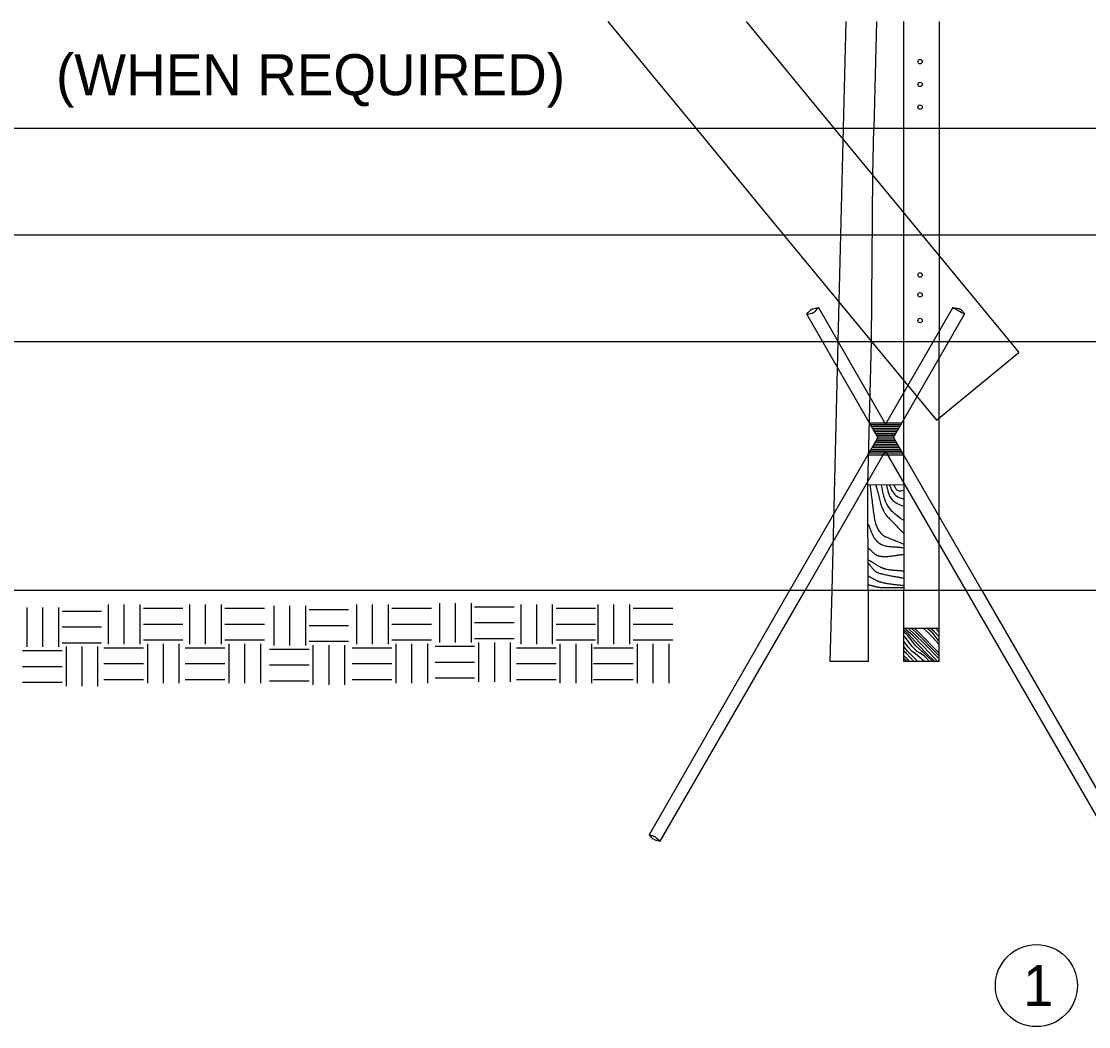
# Model space of a CAD drawing. Extents: x 49991 to 79985, y 47703 to 60542.
# Drawn here: x 50002.281 to 50003.842, y 49994.126 to 49995.596 of the extents above; entities that cross this region are included whole.
import ezdxf

# ---------------------------------------------------------------- set-up
doc = ezdxf.new("R2010")
doc.units = 0
for name, color, linetype in [('Level 1', 7, 'Continuous'), ('Level 2', 7, 'Continuous'), ('Level 4', 7, 'Continuous')]:
    doc.layers.add(name, color=color, linetype=linetype)

msp = doc.modelspace()

# ---------------------------------------------------------------- linework, layer by layer
at = {"layer": 'Level 1'}
for p, q in [((50001.0799, 49995.4403), (50005.0548, 49995.4403)), ((50003.2675, 49995.4403), (50003.396, 49995.2843)), ((50003.4696, 49995.4403), (50003.5981, 49995.2843)), ((50003.5263, 49995.3715), (50003.5281, 49995.4403)), ((50003.5716, 49995.3165), (50003.5716, 49995.4403)), ((50003.6236, 49995.4403), (50003.6236, 49995.2843)), ((50001.0799, 49995.2843), (50005.3418, 49995.2843)), ((50003.4468, 49995.1778), (50003.5452, 49995.0075)), ((50003.6436, 49995.1778), (50003.5452, 49995.0075)), ((50003.5339, 49994.9879), (50003.4299, 49995.1681)), ((50003.5565, 49994.988), (50003.6604, 49995.1681)), ((50001.0799, 49995.1283), (50005.2215, 49995.1283)), ((50003.4668, 49994.7643), (50003.4759, 49995.1283)), ((50003.5193, 49994.9188), (50003.5245, 49995.1283)), ((50003.5245, 49995.1283), (50003.6196, 49995.013)), ((50003.7266, 49995.1283), (50003.7399, 49995.1121)), ((50003.6196, 49995.013), (50003.7399, 49995.1121)), ((50003.5716, 49994.9189), (50003.5716, 49995.0712)), ((50003.6236, 49994.7643), (50003.6236, 49995.0164)), ((50003.5216, 49995.0095), (50003.5689, 49995.0095)), ((50003.5229, 49995.0069), (50003.5674, 49995.0069)), ((50003.5244, 49995.0043), (50003.5659, 49995.0043)), ((50003.5259, 49995.0017), (50003.5644, 49995.0017)), ((50003.5274, 49994.9991), (50003.5629, 49994.9991)), ((50003.5339, 49994.9879), (50003.4048, 49994.7643)), ((50003.5289, 49994.9965), (50003.5614, 49994.9965)), ((50003.5304, 49994.9939), (50003.5599, 49994.9939)), ((50003.5314, 49994.9835), (50003.5591, 49994.9835)), ((50003.5319, 49994.9913), (50003.5584, 49994.9913)), ((50003.5329, 49994.9861), (50003.5576, 49994.9861)), ((50003.5334, 49994.9887), (50003.5569, 49994.9887)), ((50003.5565, 49994.988), (50003.6857, 49994.7643)), ((50003.4274, 49994.7643), (50003.5452, 49994.9684)), ((50003.5223, 49994.9679), (50003.5681, 49994.9679)), ((50003.5239, 49994.9705), (50003.5666, 49994.9705)), ((50003.5254, 49994.9731), (50003.5651, 49994.9731)), ((50003.5269, 49994.9757), (50003.5636, 49994.9757)), ((50003.5284, 49994.9783), (50003.5621, 49994.9783)), ((50003.5299, 49994.9809), (50003.5606, 49994.9809)), ((50003.6631, 49994.7643), (50003.5452, 49994.9684)), ((50003.5193, 49994.9627), (50003.5711, 49994.9627)), ((50003.5208, 49994.9653), (50003.5696, 49994.9653)), ((50007.8111, 49994.7643), (50000.0394, 49994.7643)), ((50002.2893, 49994.7395), (50002.2893, 49994.6816)), ((50002.3124, 49994.7395), (50002.3124, 49994.6816)), ((50002.3356, 49994.7395), (50002.3356, 49994.6816)), ((50002.3409, 49994.7341), (50002.3987, 49994.7341)), ((50002.4083, 49994.7436), (50002.4083, 49994.6858)), ((50002.4314, 49994.7436), (50002.4314, 49994.6858)), ((50002.4546, 49994.7436), (50002.4546, 49994.6858)), ((50002.4599, 49994.7383), (50002.5177, 49994.7383)), ((50002.5273, 49994.7436), (50002.5273, 49994.6858)), ((50002.5504, 49994.7436), (50002.5504, 49994.6858)), ((50002.5735, 49994.7436), (50002.5735, 49994.6858)), ((50002.5789, 49994.7383), (50002.6367, 49994.7383)), ((50002.6504, 49994.7416), (50002.6504, 49994.6837)), ((50002.6736, 49994.7416), (50002.6736, 49994.6837)), ((50002.6967, 49994.7416), (50002.6967, 49994.6837)), ((50002.7021, 49994.7362), (50002.7599, 49994.7362)), ((50002.7715, 49994.7436), (50002.7715, 49994.6858)), ((50002.7946, 49994.7436), (50002.7946, 49994.6858)), ((50002.8178, 49994.7436), (50002.8178, 49994.6858)), ((50002.8231, 49994.7383), (50002.881, 49994.7383)), ((50002.8926, 49994.7457), (50002.8926, 49994.6879)), ((50002.9157, 49994.7457), (50002.9157, 49994.6879)), ((50002.9389, 49994.7457), (50002.9389, 49994.6879)), ((50002.9442, 49994.7403), (50003.002, 49994.7403)), ((50003.0116, 49994.7436), (50003.0116, 49994.6858)), ((50003.0347, 49994.7436), (50003.0347, 49994.6858)), ((50003.0578, 49994.7436), (50003.0578, 49994.6858)), ((50003.0632, 49994.7383), (50003.121, 49994.7383)), ((50003.1243, 49994.7436), (50003.1243, 49994.6858)), ((50003.1474, 49994.7436), (50003.1474, 49994.6858)), ((50003.1706, 49994.7436), (50003.1706, 49994.6858)), ((50003.1759, 49994.7383), (50003.2338, 49994.7383)), ((50002.3409, 49994.711), (50002.3987, 49994.711)), ((50002.4599, 49994.7151), (50002.5177, 49994.7151)), ((50002.5789, 49994.7151), (50002.6367, 49994.7151)), ((50002.7021, 49994.7131), (50002.7599, 49994.7131)), ((50002.8231, 49994.7151), (50002.881, 49994.7151)), ((50002.9442, 49994.7172), (50003.002, 49994.7172)), ((50003.0632, 49994.7151), (50003.121, 49994.7151)), ((50003.1759, 49994.7151), (50003.2338, 49994.7151)), ((50002.3409, 49994.6878), (50002.3987, 49994.6878)), ((50002.4599, 49994.692), (50002.5177, 49994.692)), ((50002.5789, 49994.692), (50002.6367, 49994.692)), ((50002.7021, 49994.6899), (50002.7599, 49994.6899)), ((50002.8231, 49994.692), (50002.881, 49994.692)), ((50002.9442, 49994.6941), (50003.002, 49994.6941)), ((50002.95, 49994.6883), (50002.95, 49994.6305)), ((50002.9731, 49994.6883), (50002.9731, 49994.6305)), ((50002.9962, 49994.6883), (50002.9962, 49994.6305)), ((50003.0632, 49994.692), (50003.121, 49994.692)), ((50003.1759, 49994.692), (50003.2338, 49994.692)), ((50002.2831, 49994.6763), (50002.3409, 49994.6763)), ((50002.3467, 49994.6821), (50002.3467, 49994.6242)), ((50002.3698, 49994.6821), (50002.3698, 49994.6242)), ((50002.3929, 49994.6821), (50002.3929, 49994.6242)), ((50002.4021, 49994.6804), (50002.4599, 49994.6804)), ((50002.4657, 49994.6862), (50002.4657, 49994.6284)), ((50002.4888, 49994.6862), (50002.4888, 49994.6284)), ((50002.5119, 49994.6862), (50002.5119, 49994.6284)), ((50002.5211, 49994.6804), (50002.5789, 49994.6804)), ((50002.5847, 49994.6862), (50002.5847, 49994.6284)), ((50002.6078, 49994.6862), (50002.6078, 49994.6284)), ((50002.6309, 49994.6862), (50002.6309, 49994.6284)), ((50002.6442, 49994.6783), (50002.7021, 49994.6783)), ((50002.7078, 49994.6841), (50002.7078, 49994.6263)), ((50002.731, 49994.6841), (50002.731, 49994.6263)), ((50002.7541, 49994.6841), (50002.7541, 49994.6263)), ((50002.7653, 49994.6804), (50002.8231, 49994.6804)), ((50002.8289, 49994.6862), (50002.8289, 49994.6284)), ((50002.852, 49994.6862), (50002.852, 49994.6284)), ((50002.8752, 49994.6862), (50002.8752, 49994.6284)), ((50002.8864, 49994.6825), (50002.9442, 49994.6825)), ((50003.0054, 49994.6804), (50003.0632, 49994.6804)), ((50003.069, 49994.6862), (50003.069, 49994.6284)), ((50003.0921, 49994.6862), (50003.0921, 49994.6284)), ((50003.1152, 49994.6862), (50003.1152, 49994.6284)), ((50003.1181, 49994.6804), (50003.1759, 49994.6804)), ((50003.1817, 49994.6862), (50003.1817, 49994.6284)), ((50003.2048, 49994.6862), (50003.2048, 49994.6284)), ((50003.228, 49994.6862), (50003.228, 49994.6284)), ((50002.4021, 49994.6573), (50002.4599, 49994.6573)), ((50002.5211, 49994.6573), (50002.5789, 49994.6573)), ((50002.6442, 49994.6552), (50002.7021, 49994.6552)), ((50002.7653, 49994.6573), (50002.8231, 49994.6573)), ((50002.8864, 49994.6594), (50002.9442, 49994.6594)), ((50003.0054, 49994.6573), (50003.0632, 49994.6573)), ((50003.1181, 49994.6573), (50003.1759, 49994.6573)), ((50002.2831, 49994.6532), (50002.3409, 49994.6532)), ((50002.2831, 49994.63), (50002.3409, 49994.63)), ((50002.4021, 49994.6342), (50002.4599, 49994.6342)), ((50002.5211, 49994.6342), (50002.5789, 49994.6342)), ((50002.6442, 49994.6321), (50002.7021, 49994.6321)), ((50002.7653, 49994.6342), (50002.8231, 49994.6342)), ((50002.8864, 49994.6363), (50002.9442, 49994.6363)), ((50003.0054, 49994.6342), (50003.0632, 49994.6342)), ((50003.1181, 49994.6342), (50003.1759, 49994.6342))]:
    msp.add_line(p, q, dxfattribs=at)
msp.add_lwpolyline([(50003.5196, 49994.7643), (50003.5193, 49994.9188), (50003.5716, 49994.9189), (50003.5716, 49994.7643)], close=True, dxfattribs=at)
for centre in [(50003.5955, 49995.5374), (50003.5955, 49995.5041), (50003.5955, 49995.4708), (50003.5955, 49995.2255), (50003.5955, 49995.1964), (50003.5955, 49995.1589)]:
    msp.add_circle(centre, 0.00327, dxfattribs=at)
for points in [[(50003.4299, 49995.1681), (50003.4401, 49995.1709), (50003.4468, 49995.1778)], [(50003.4299, 49995.1681), (50003.4379, 49995.1758), (50003.4468, 49995.1778)], [(50003.6436, 49995.1778), (50003.6551, 49995.1751), (50003.6604, 49995.1681)], [(50003.6436, 49995.1778), (50003.652, 49995.1732), (50003.6604, 49995.1681)], [(50003.5386, 49994.9187), (50003.5484, 49994.8875), (50003.5707, 49994.8673)], [(50003.5464, 49994.9184), (50003.5545, 49994.8969), (50003.5714, 49994.8875)], [(50003.5505, 49994.9186), (50003.5619, 49994.9016), (50003.5707, 49994.8982)], [(50003.5568, 49994.9187), (50003.5646, 49994.9097), (50003.5707, 49994.911)]]:
    msp.add_spline(points, degree=3, dxfattribs=at)
for points in [[(50003.5222, 49994.9188), (50003.5242, 49994.9034), (50003.5262, 49994.8881), (50003.5282, 49994.8727), (50003.5283, 49994.872), (50003.5284, 49994.8712), (50003.5285, 49994.8705), (50003.5286, 49994.8698), (50003.5288, 49994.869), (50003.5289, 49994.8683), (50003.5292, 49994.8667), (50003.5296, 49994.8652), (50003.5301, 49994.8637), (50003.5309, 49994.8607), (50003.5321, 49994.8578), (50003.5335, 49994.8549), (50003.5348, 49994.8521), (50003.5365, 49994.8497), (50003.5386, 49994.8474), (50003.5396, 49994.8463), (50003.5407, 49994.8454), (50003.5419, 49994.8446), (50003.5425, 49994.8442), (50003.5431, 49994.8438), (50003.5437, 49994.8434), (50003.5444, 49994.8431), (50003.545, 49994.8428), (50003.5457, 49994.8425), (50003.5543, 49994.839), (50003.563, 49994.8356), (50003.5716, 49994.8321)], [(50003.5304, 49994.9187), (50003.5306, 49994.9182), (50003.5308, 49994.9177), (50003.5309, 49994.9172), (50003.5311, 49994.9167), (50003.5313, 49994.9162), (50003.5315, 49994.9157), (50003.5318, 49994.9147), (50003.5321, 49994.9137), (50003.5324, 49994.9126), (50003.533, 49994.9105), (50003.5335, 49994.9084), (50003.5341, 49994.9064), (50003.5352, 49994.9021), (50003.5361, 49994.8979), (50003.5372, 49994.8937), (50003.5383, 49994.8896), (50003.5397, 49994.8856), (50003.5415, 49994.8817), (50003.5423, 49994.8798), (50003.5433, 49994.878), (50003.5445, 49994.8763), (50003.5451, 49994.8754), (50003.5457, 49994.8746), (50003.5463, 49994.8737), (50003.5467, 49994.8733), (50003.547, 49994.8729), (50003.5473, 49994.8726), (50003.5477, 49994.8722), (50003.548, 49994.8718), (50003.5484, 49994.8714), (50003.5561, 49994.8635), (50003.5639, 49994.8555), (50003.5716, 49994.8476)], [(50003.5194, 49994.8613), (50003.52, 49994.8602), (50003.5205, 49994.8591), (50003.521, 49994.858), (50003.5214, 49994.8569), (50003.5219, 49994.8558), (50003.5223, 49994.8547), (50003.5232, 49994.8525), (50003.5241, 49994.8503), (50003.525, 49994.848), (50003.5259, 49994.8458), (50003.527, 49994.8437), (50003.5282, 49994.8416), (50003.5288, 49994.8405), (50003.5295, 49994.8395), (50003.5303, 49994.8386), (50003.5307, 49994.8381), (50003.5311, 49994.8376), (50003.5315, 49994.8371), (50003.5318, 49994.8369), (50003.532, 49994.8366), (50003.5322, 49994.8364), (50003.5323, 49994.8363), (50003.5324, 49994.8362), (50003.5325, 49994.836), (50003.5326, 49994.836), (50003.5327, 49994.8359), (50003.5327, 49994.8359), (50003.5328, 49994.8358), (50003.5328, 49994.8358), (50003.5328, 49994.8358), (50003.5328, 49994.8358), (50003.5329, 49994.8357), (50003.5329, 49994.8357), (50003.5332, 49994.8354), (50003.5336, 49994.8351), (50003.5339, 49994.8348), (50003.5342, 49994.8345), (50003.5346, 49994.8342), (50003.5349, 49994.834), (50003.5356, 49994.8334), (50003.5363, 49994.833), (50003.537, 49994.8325), (50003.5384, 49994.8317), (50003.5399, 49994.8309), (50003.5415, 49994.8304), (50003.5447, 49994.8294), (50003.5479, 49994.8287), (50003.5513, 49994.8284), (50003.5546, 49994.8282), (50003.558, 49994.828), (50003.5614, 49994.8278), (50003.5631, 49994.8276), (50003.5648, 49994.8275), (50003.5665, 49994.8273), (50003.5681, 49994.8271), (50003.5698, 49994.8268), (50003.5714, 49994.8264)], [(50003.5195, 49994.8263), (50003.5201, 49994.8259), (50003.5208, 49994.8254), (50003.5214, 49994.8248), (50003.522, 49994.8243), (50003.5226, 49994.8237), (50003.5232, 49994.8232), (50003.5244, 49994.822), (50003.5255, 49994.8209), (50003.5267, 49994.8198), (50003.5279, 49994.8187), (50003.5292, 49994.8177), (50003.5305, 49994.8168), (50003.5312, 49994.8163), (50003.5319, 49994.816), (50003.5326, 49994.8157), (50003.533, 49994.8155), (50003.5334, 49994.8154), (50003.5337, 49994.8152), (50003.5339, 49994.8152), (50003.5341, 49994.8151), (50003.5343, 49994.8151), (50003.5344, 49994.815), (50003.5345, 49994.815), (50003.5346, 49994.815), (50003.5347, 49994.815), (50003.5347, 49994.8149), (50003.5348, 49994.8149), (50003.5348, 49994.8149), (50003.5349, 49994.8149), (50003.5349, 49994.8149), (50003.5379, 49994.8142), (50003.541, 49994.8139), (50003.5441, 49994.8139), (50003.5472, 49994.8139), (50003.5503, 49994.8141), (50003.5534, 49994.8145), (50003.5565, 49994.815), (50003.5596, 49994.8155), (50003.5627, 49994.8159), (50003.5643, 49994.8161), (50003.5658, 49994.8163), (50003.5674, 49994.8165), (50003.5688, 49994.8167), (50003.5702, 49994.8168), (50003.5716, 49994.8169)], [(50003.5195, 49994.8092), (50003.5205, 49994.8087), (50003.5215, 49994.8081), (50003.5225, 49994.8075), (50003.5235, 49994.8069), (50003.5244, 49994.8063), (50003.5254, 49994.8057), (50003.5274, 49994.8045), (50003.5293, 49994.8032), (50003.5313, 49994.802), (50003.5332, 49994.8008), (50003.5352, 49994.7997), (50003.5373, 49994.7987), (50003.5383, 49994.7981), (50003.5394, 49994.7977), (50003.5404, 49994.7973), (50003.541, 49994.797), (50003.5415, 49994.7968), (50003.542, 49994.7966), (50003.5423, 49994.7965), (50003.5426, 49994.7965), (50003.5429, 49994.7964), (50003.543, 49994.7963), (50003.5431, 49994.7963), (50003.5433, 49994.7962), (50003.5434, 49994.7962), (50003.5434, 49994.7962), (50003.5435, 49994.7962), (50003.5436, 49994.7961), (50003.5436, 49994.7961), (50003.5437, 49994.7961), (50003.5459, 49994.7954), (50003.5482, 49994.7949), (50003.5505, 49994.7946), (50003.5529, 49994.7943), (50003.5552, 49994.794), (50003.5575, 49994.7939), (50003.5598, 49994.7937), (50003.5621, 49994.7936), (50003.5645, 49994.7934), (50003.5656, 49994.7933), (50003.5668, 49994.7933), (50003.5679, 49994.7932), (50003.5691, 49994.7931), (50003.5702, 49994.7929), (50003.5714, 49994.7928)], [(50003.5195, 49994.8041), (50003.5201, 49994.8035), (50003.5207, 49994.8029), (50003.5213, 49994.8022), (50003.5219, 49994.8015), (50003.5224, 49994.8009), (50003.523, 49994.8002), (50003.5241, 49994.7988), (50003.5252, 49994.7974), (50003.5263, 49994.7961), (50003.5274, 49994.7948), (50003.5286, 49994.7936), (50003.5299, 49994.7925), (50003.5306, 49994.7919), (50003.5312, 49994.7915), (50003.532, 49994.7911), (50003.5324, 49994.7909), (50003.5327, 49994.7907), (50003.5331, 49994.7905), (50003.5333, 49994.7905), (50003.5335, 49994.7904), (50003.5337, 49994.7903), (50003.5338, 49994.7903), (50003.5339, 49994.7902), (50003.534, 49994.7902), (50003.5341, 49994.7902), (50003.5342, 49994.7901), (50003.5343, 49994.7901), (50003.5374, 49994.7892), (50003.5405, 49994.7883), (50003.5437, 49994.7876), (50003.5468, 49994.7869), (50003.5499, 49994.7862), (50003.5531, 49994.7856), (50003.5562, 49994.785), (50003.5594, 49994.7845), (50003.5626, 49994.7839), (50003.5641, 49994.7836), (50003.5657, 49994.7833), (50003.5673, 49994.783), (50003.5687, 49994.7827), (50003.5702, 49994.7824), (50003.5716, 49994.7821)], [(50003.5196, 49994.7853), (50003.5203, 49994.785), (50003.5211, 49994.7846), (50003.5218, 49994.7842), (50003.5225, 49994.7838), (50003.5233, 49994.7834), (50003.524, 49994.783), (50003.5255, 49994.7822), (50003.5269, 49994.7814), (50003.5284, 49994.7805), (50003.5299, 49994.7797), (50003.5314, 49994.779), (50003.5329, 49994.7783), (50003.5336, 49994.778), (50003.5344, 49994.7777), (50003.5352, 49994.7774), (50003.5356, 49994.7772), (50003.536, 49994.7771), (50003.5364, 49994.777), (50003.5366, 49994.7769), (50003.5368, 49994.7768), (50003.537, 49994.7768), (50003.5371, 49994.7767), (50003.5372, 49994.7767), (50003.5373, 49994.7767), (50003.5374, 49994.7767), (50003.5375, 49994.7766), (50003.5376, 49994.7766), (50003.5404, 49994.7758), (50003.5433, 49994.7752), (50003.5461, 49994.7747), (50003.549, 49994.7742), (50003.5519, 49994.7738), (50003.5547, 49994.7735), (50003.5576, 49994.7731), (50003.5605, 49994.7728), (50003.5634, 49994.7724), (50003.5648, 49994.7723), (50003.5663, 49994.7721), (50003.5677, 49994.7719), (50003.569, 49994.7717), (50003.5703, 49994.7716), (50003.5716, 49994.7714)], [(50003.5196, 49994.7726), (50003.5204, 49994.7724), (50003.5213, 49994.7722), (50003.5221, 49994.772), (50003.5229, 49994.7718), (50003.5238, 49994.7716), (50003.5246, 49994.7714), (50003.5263, 49994.7709), (50003.5279, 49994.7705), (50003.5296, 49994.7701), (50003.5312, 49994.7696), (50003.5329, 49994.7693), (50003.5346, 49994.769), (50003.5363, 49994.7688), (50003.538, 49994.7686), (50003.5397, 49994.7686), (50003.55, 49994.7686), (50003.5604, 49994.7686), (50003.5707, 49994.7686)]]:
    msp.add_open_spline(points, degree=3, dxfattribs=at)
at = {"layer": 'Level 2'}
msp.add_circle((50003.7657, 49994.1864), 0.06, dxfattribs=at)
at = {"layer": 'Level 4'}
for p, q in [((50003.139, 49995.5963), (50003.2675, 49995.4403)), ((50003.3411, 49995.5963), (50003.4696, 49995.4403)), ((50003.4759, 49995.1283), (50003.4876, 49995.5963)), ((50003.5319, 49995.5963), (50003.5281, 49995.4403)), ((50003.5716, 49995.4403), (50003.5716, 49995.5963)), ((50003.6236, 49995.5963), (50003.6236, 49995.4403)), ((50003.5245, 49995.1283), (50003.5263, 49995.3715)), ((50003.5716, 49995.0712), (50003.5716, 49995.3165)), ((50003.396, 49995.2843), (50003.5245, 49995.1283)), ((50003.5981, 49995.2843), (50003.7266, 49995.1283)), ((50003.6236, 49995.2843), (50003.6236, 49995.1283)), ((50003.6236, 49995.0164), (50003.6236, 49995.1283)), ((50003.4048, 49994.7643), (50003.1992, 49994.4067)), ((50003.2155, 49994.3977), (50003.4274, 49994.7643)), ((50003.4643, 49994.6603), (50003.4668, 49994.7643)), ((50003.5196, 49994.7643), (50003.5196, 49994.6603)), ((50003.5716, 49994.6603), (50003.5716, 49994.7643)), ((50003.6236, 49994.7092), (50003.6236, 49994.7643)), ((50003.8748, 49994.3976), (50003.6631, 49994.7643)), ((50003.6857, 49994.7643), (50003.8919, 49994.407)), ((50003.5716, 49994.7092), (50003.6236, 49994.7092)), ((50003.6236, 49994.6603), (50003.6236, 49994.7092)), ((50003.5196, 49994.6603), (50003.4643, 49994.6603))]:
    msp.add_line(p, q, dxfattribs=at)
for points in [[(50003.6172, 49994.6603), (50003.6048, 49994.6721), (50003.5932, 49994.684), (50003.5786, 49994.7002), (50003.5716, 49994.7067)], [(50003.6141, 49994.6603), (50003.6034, 49994.6706), (50003.5892, 49994.6831), (50003.5771, 49994.6987), (50003.5716, 49994.7038)], [(50003.6211, 49994.6603), (50003.6164, 49994.6653), (50003.6, 49994.6828), (50003.5843, 49994.6986), (50003.5757, 49994.7063), (50003.5724, 49994.7092)], [(50003.6236, 49994.6642), (50003.6217, 49994.6661), (50003.6004, 49994.6877), (50003.5782, 49994.7092)], [(50003.6236, 49994.6684), (50003.5881, 49994.7045), (50003.5829, 49994.7092)], [(50003.6236, 49994.6726), (50003.6156, 49994.6804), (50003.6017, 49994.6949), (50003.5874, 49994.709), (50003.5872, 49994.7092)], [(50003.6236, 49994.685), (50003.6089, 49994.7014), (50003.6002, 49994.7092)], [(50003.6236, 49994.6901), (50003.6226, 49994.6912), (50003.6143, 49994.7016), (50003.6055, 49994.7092)], [(50003.6236, 49994.6962), (50003.6163, 49994.704), (50003.6101, 49994.7092)], [(50003.6236, 49994.7033), (50003.6182, 49994.7092)], [(50003.6236, 49994.7088), (50003.6233, 49994.7092)], [(50003.6091, 49994.6603), (50003.6018, 49994.6679), (50003.5956, 49994.6724), (50003.5912, 49994.675), (50003.5836, 49994.6826), (50003.574, 49994.6956), (50003.5716, 49994.6979)], [(50003.6018, 49994.6603), (50003.5953, 49994.6663), (50003.5889, 49994.6714), (50003.5839, 49994.6751), (50003.5775, 49994.6818), (50003.5731, 49994.6881), (50003.5716, 49994.6898)], [(50003.5922, 49994.6603), (50003.5772, 49994.6756), (50003.5716, 49994.682)], [(50003.5866, 49994.6603), (50003.5755, 49994.6722), (50003.5716, 49994.6754)], [(50003.58, 49994.6603), (50003.5765, 49994.6641), (50003.5716, 49994.6681)], [(50003.5756, 49994.6603), (50003.5745, 49994.6617), (50003.5716, 49994.6641)], [(50003.6236, 49994.6603), (50003.5716, 49994.6603)]]:
    msp.add_lwpolyline(points, dxfattribs=at)
for points in [[(50003.1992, 49994.4067), (50003.2071, 49994.3999), (50003.2155, 49994.3977)], [(50003.1992, 49994.4067), (50003.1998, 49994.4065), (50003.2011, 49994.4063), (50003.2018, 49994.4061), (50003.2025, 49994.406), (50003.2038, 49994.4057), (50003.2045, 49994.4056), (50003.2051, 49994.4054), (50003.2057, 49994.4052), (50003.206, 49994.4051), (50003.2064, 49994.4049), (50003.2075, 49994.4044), (50003.2086, 49994.4036), (50003.2155, 49994.3977)]]:
    msp.add_spline(points, degree=3, dxfattribs=at)

# ---------------------------------------------------------------- texts
at = {"layer": 'Level 2'}
for s, p in [('(WHEN REQUIRED)', (50002.3321, 49995.4883)), ('1', (50003.746, 49994.1564))]:
    msp.add_text(s, height=0.06, dxfattribs=at).set_placement(p)

doc.saveas('drawing.dxf')
